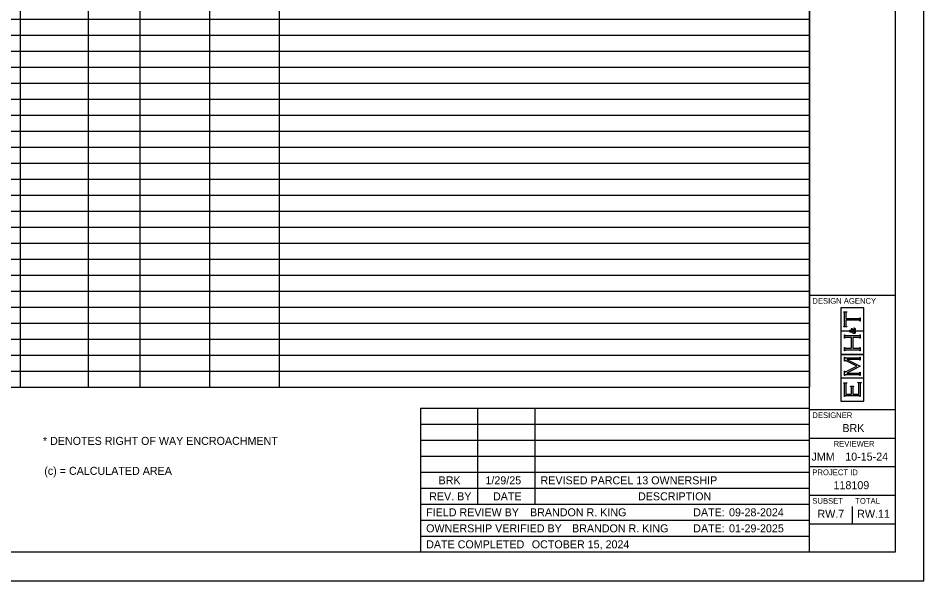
# Model space of a CAD drawing. Extents: x 0 to 34, y 0 to 22.
# Drawn here: x 18.16 to 34, y 0 to 9.85 of the extents above; entities that cross this region are included whole.
import ezdxf

# ---------------------------------------------------------------- set-up
doc = ezdxf.new("R2010")
doc.units = 0
for name, color, linetype in [('SH_Border', 7, 'Continuous'), ('SH_Cut_Line', 7, 'Continuous'), ('SH_Data', 7, 'Continuous'), ('SH_Text', 7, 'Continuous')]:
    doc.layers.add(name, color=color, linetype=linetype)

msp = doc.modelspace()

# ---------------------------------------------------------------- linework, layer by layer
at = {"layer": 'SH_Border'}
for p, q in [((32, 0.5), (32, 21.5)), ((32, 5), (33.5, 5)), ((32, 3), (33.5, 3)), ((32, 2.5), (33.5, 2.5)), ((32, 2), (33.5, 2)), ((32, 1.5), (33.5, 1.5)), ((32, 1), (33.5, 1))]:
    msp.add_line(p, q, dxfattribs=at)
msp.add_lwpolyline([(1.5, 21.5), (33.5, 21.5), (33.5, 0.5), (1.5, 0.5)], close=True, dxfattribs=at)
at = {"layer": 'SH_Cut_Line'}
msp.add_lwpolyline([(0, 0), (34, 0), (34, 22), (0, 22)], close=True, dxfattribs=at)
at = {"layer": 'SH_Data'}
for p, q in [((32.952, 4.779), (32.547, 4.779)), ((32.547, 4.779), (32.547, 4.375)), ((32.952, 4.375), (32.952, 4.779)), ((32.598, 4.704), (32.598, 4.711)), ((32.598, 4.711), (32.65, 4.711)), ((32.603, 4.703), (32.598, 4.704)), ((32.606, 4.701), (32.603, 4.703)), ((32.608, 4.699), (32.606, 4.701)), ((32.61, 4.696), (32.608, 4.699)), ((32.611, 4.692), (32.61, 4.696)), ((32.611, 4.687), (32.611, 4.692)), ((32.611, 4.468), (32.611, 4.687)), ((32.638, 4.696), (32.637, 4.692)), ((32.637, 4.692), (32.637, 4.687)), ((32.637, 4.687), (32.637, 4.593)), ((32.637, 4.593), (32.864, 4.593)), ((32.64, 4.699), (32.638, 4.696)), ((32.642, 4.701), (32.64, 4.699)), ((32.645, 4.703), (32.642, 4.701)), ((32.65, 4.704), (32.645, 4.703)), ((32.65, 4.711), (32.65, 4.704)), ((32.864, 4.593), (32.869, 4.593)), ((32.869, 4.593), (32.873, 4.594)), ((32.873, 4.594), (32.876, 4.596)), ((32.876, 4.596), (32.878, 4.597)), ((32.878, 4.597), (32.88, 4.601)), ((32.88, 4.601), (32.881, 4.606)), ((32.881, 4.606), (32.888, 4.606)), ((32.888, 4.606), (32.888, 4.548)), ((32.598, 4.45), (32.603, 4.451)), ((32.598, 4.444), (32.598, 4.45)), ((32.65, 4.444), (32.598, 4.444)), ((32.603, 4.451), (32.606, 4.453)), ((32.606, 4.453), (32.608, 4.455)), ((32.608, 4.455), (32.61, 4.458)), ((32.61, 4.458), (32.611, 4.462)), ((32.611, 4.462), (32.611, 4.468)), ((32.864, 4.561), (32.637, 4.561)), ((32.637, 4.561), (32.637, 4.468)), ((32.637, 4.468), (32.637, 4.462)), ((32.637, 4.462), (32.638, 4.458)), ((32.638, 4.458), (32.64, 4.455)), ((32.64, 4.455), (32.642, 4.453)), ((32.642, 4.453), (32.645, 4.451)), ((32.645, 4.451), (32.65, 4.45)), ((32.65, 4.45), (32.65, 4.444)), ((32.87, 4.561), (32.864, 4.561)), ((32.874, 4.56), (32.87, 4.561)), ((32.876, 4.559), (32.874, 4.56)), ((32.878, 4.557), (32.876, 4.559)), ((32.88, 4.553), (32.878, 4.557)), ((32.881, 4.548), (32.88, 4.553)), ((32.888, 4.548), (32.881, 4.548)), ((32.547, 4.375), (32.696, 4.375)), ((32.696, 4.369), (32.547, 4.369)), ((32.547, 4.369), (32.547, 3.965)), ((32.611, 4.249), (32.611, 4.307)), ((32.611, 4.307), (32.617, 4.307)), ((32.617, 4.307), (32.619, 4.302)), ((32.619, 4.302), (32.62, 4.298)), ((32.62, 4.298), (32.623, 4.297)), ((32.623, 4.297), (32.625, 4.295)), ((32.625, 4.295), (32.629, 4.294)), ((32.629, 4.294), (32.635, 4.294)), ((32.635, 4.294), (32.864, 4.294)), ((32.696, 4.375), (32.696, 4.369)), ((32.703, 4.379), (32.705, 4.383)), ((32.703, 4.373), (32.703, 4.379)), ((32.703, 4.368), (32.703, 4.373)), ((32.705, 4.363), (32.703, 4.368)), ((32.705, 4.383), (32.708, 4.387)), ((32.708, 4.358), (32.705, 4.363)), ((32.708, 4.387), (32.711, 4.39)), ((32.709, 4.379), (32.708, 4.376)), ((32.708, 4.376), (32.708, 4.373)), ((32.708, 4.373), (32.708, 4.369)), ((32.708, 4.369), (32.71, 4.366)), ((32.712, 4.353), (32.708, 4.358)), ((32.712, 4.381), (32.709, 4.379)), ((32.71, 4.366), (32.712, 4.364)), ((32.711, 4.39), (32.715, 4.392)), ((32.714, 4.383), (32.712, 4.381)), ((32.712, 4.364), (32.715, 4.362)), ((32.718, 4.35), (32.712, 4.353)), ((32.716, 4.384), (32.714, 4.383)), ((32.715, 4.392), (32.72, 4.392)), ((32.715, 4.362), (32.718, 4.361)), ((32.72, 4.384), (32.716, 4.384)), ((32.718, 4.361), (32.721, 4.361)), ((32.726, 4.35), (32.718, 4.35)), ((32.72, 4.392), (32.725, 4.392)), ((32.724, 4.384), (32.72, 4.384)), ((32.721, 4.361), (32.723, 4.361)), ((32.723, 4.361), (32.725, 4.362)), ((32.728, 4.382), (32.724, 4.384)), ((32.725, 4.392), (32.729, 4.39)), ((32.725, 4.362), (32.728, 4.362)), ((32.729, 4.35), (32.726, 4.35)), ((32.731, 4.38), (32.728, 4.382)), ((32.728, 4.362), (32.731, 4.363)), ((32.729, 4.39), (32.732, 4.387)), ((32.731, 4.35), (32.729, 4.35)), ((32.734, 4.377), (32.731, 4.38)), ((32.731, 4.363), (32.735, 4.365)), ((32.734, 4.351), (32.731, 4.35)), ((32.732, 4.387), (32.736, 4.383)), ((32.737, 4.372), (32.734, 4.377)), ((32.737, 4.352), (32.734, 4.351)), ((32.735, 4.365), (32.74, 4.367)), ((32.736, 4.383), (32.74, 4.378)), ((32.74, 4.367), (32.737, 4.372)), ((32.741, 4.353), (32.737, 4.352)), ((32.738, 4.393), (32.738, 4.422)), ((32.738, 4.422), (32.741, 4.422)), ((32.741, 4.393), (32.738, 4.393)), ((32.74, 4.378), (32.744, 4.369)), ((32.741, 4.422), (32.741, 4.418)), ((32.741, 4.418), (32.742, 4.415)), ((32.742, 4.396), (32.741, 4.395)), ((32.741, 4.395), (32.741, 4.393)), ((32.746, 4.355), (32.741, 4.353)), ((32.742, 4.415), (32.743, 4.413)), ((32.743, 4.397), (32.742, 4.396)), ((32.743, 4.413), (32.745, 4.411)), ((32.745, 4.399), (32.743, 4.397)), ((32.744, 4.369), (32.754, 4.375)), ((32.745, 4.411), (32.749, 4.408)), ((32.746, 4.399), (32.745, 4.399)), ((32.748, 4.399), (32.746, 4.399)), ((32.752, 4.344), (32.746, 4.355)), ((32.755, 4.399), (32.748, 4.399)), ((32.749, 4.408), (32.756, 4.404)), ((32.756, 4.36), (32.751, 4.357)), ((32.751, 4.357), (32.754, 4.352)), ((32.757, 4.337), (32.752, 4.344)), ((32.754, 4.375), (32.764, 4.381)), ((32.754, 4.352), (32.757, 4.348)), ((32.763, 4.395), (32.755, 4.399)), ((32.756, 4.404), (32.763, 4.4)), ((32.761, 4.363), (32.756, 4.36)), ((32.757, 4.348), (32.761, 4.345)), ((32.763, 4.333), (32.757, 4.337)), ((32.764, 4.365), (32.761, 4.363)), ((32.761, 4.345), (32.765, 4.343)), ((32.763, 4.4), (32.77, 4.396)), ((32.772, 4.387), (32.763, 4.395)), ((32.768, 4.329), (32.763, 4.333)), ((32.764, 4.381), (32.772, 4.387)), ((32.768, 4.367), (32.764, 4.365)), ((32.765, 4.343), (32.769, 4.341)), ((32.774, 4.372), (32.768, 4.367)), ((32.774, 4.327), (32.768, 4.329)), ((32.769, 4.341), (32.773, 4.341)), ((32.77, 4.396), (32.776, 4.391)), ((32.773, 4.341), (32.778, 4.341)), ((32.782, 4.378), (32.774, 4.372)), ((32.779, 4.327), (32.774, 4.327)), ((32.776, 4.391), (32.781, 4.395)), ((32.778, 4.341), (32.782, 4.343)), ((32.779, 4.423), (32.781, 4.426)), ((32.782, 4.422), (32.779, 4.423)), ((32.785, 4.327), (32.779, 4.327)), ((32.781, 4.426), (32.787, 4.424)), ((32.781, 4.395), (32.784, 4.398)), ((32.785, 4.421), (32.782, 4.422)), ((32.786, 4.373), (32.782, 4.378)), ((32.782, 4.343), (32.786, 4.346)), ((32.784, 4.398), (32.786, 4.401)), ((32.786, 4.419), (32.785, 4.421)), ((32.79, 4.329), (32.785, 4.327)), ((32.788, 4.417), (32.786, 4.419)), ((32.786, 4.401), (32.788, 4.404)), ((32.791, 4.386), (32.786, 4.381)), ((32.786, 4.381), (32.791, 4.376)), ((32.788, 4.369), (32.786, 4.373)), ((32.786, 4.346), (32.789, 4.349)), ((32.787, 4.424), (32.792, 4.421)), ((32.789, 4.414), (32.788, 4.417)), ((32.788, 4.404), (32.789, 4.408)), ((32.79, 4.367), (32.788, 4.369)), ((32.789, 4.411), (32.789, 4.414)), ((32.789, 4.408), (32.789, 4.411)), ((32.789, 4.349), (32.791, 4.353)), ((32.791, 4.364), (32.79, 4.367)), ((32.793, 4.334), (32.79, 4.329)), ((32.794, 4.39), (32.791, 4.386)), ((32.791, 4.376), (32.795, 4.37)), ((32.791, 4.361), (32.791, 4.364)), ((32.791, 4.359), (32.791, 4.361)), ((32.791, 4.353), (32.791, 4.359)), ((32.792, 4.421), (32.795, 4.418)), ((32.797, 4.338), (32.793, 4.334)), ((32.796, 4.394), (32.794, 4.39)), ((32.795, 4.418), (32.798, 4.414)), ((32.795, 4.37), (32.797, 4.366)), ((32.798, 4.397), (32.796, 4.394)), ((32.797, 4.366), (32.798, 4.361)), ((32.799, 4.344), (32.797, 4.338)), ((32.798, 4.414), (32.799, 4.41)), ((32.799, 4.401), (32.798, 4.397)), ((32.798, 4.361), (32.799, 4.357)), ((32.799, 4.41), (32.799, 4.405)), ((32.799, 4.405), (32.799, 4.401)), ((32.803, 4.369), (32.799, 4.375)), ((32.799, 4.375), (32.952, 4.375)), ((32.799, 4.357), (32.799, 4.352)), ((32.799, 4.352), (32.799, 4.344)), ((32.952, 4.369), (32.803, 4.369)), ((32.864, 4.294), (32.869, 4.294)), ((32.869, 4.294), (32.873, 4.295)), ((32.873, 4.295), (32.876, 4.297)), ((32.876, 4.297), (32.878, 4.298)), ((32.878, 4.298), (32.88, 4.302)), ((32.88, 4.302), (32.881, 4.307)), ((32.881, 4.307), (32.888, 4.307)), ((32.888, 4.307), (32.888, 4.249)), ((32.952, 3.965), (32.952, 4.369)), ((32.617, 4.249), (32.611, 4.249)), ((32.618, 4.254), (32.617, 4.249)), ((32.62, 4.258), (32.618, 4.254)), ((32.623, 4.26), (32.62, 4.258)), ((32.625, 4.261), (32.623, 4.26)), ((32.629, 4.262), (32.625, 4.261)), ((32.635, 4.262), (32.629, 4.262)), ((32.732, 4.262), (32.635, 4.262)), ((32.732, 4.072), (32.732, 4.262)), ((32.864, 4.262), (32.759, 4.262)), ((32.759, 4.262), (32.759, 4.072)), ((32.87, 4.262), (32.864, 4.262)), ((32.874, 4.261), (32.87, 4.262)), ((32.876, 4.26), (32.874, 4.261)), ((32.878, 4.258), (32.876, 4.26)), ((32.88, 4.254), (32.878, 4.258)), ((32.881, 4.249), (32.88, 4.254)), ((32.888, 4.249), (32.881, 4.249)), ((32.547, 3.965), (32.952, 3.965)), ((32.611, 4.027), (32.611, 4.085)), ((32.611, 4.085), (32.617, 4.085)), ((32.617, 4.027), (32.611, 4.027)), ((32.617, 4.085), (32.619, 4.08)), ((32.618, 4.032), (32.617, 4.027)), ((32.62, 4.036), (32.618, 4.032)), ((32.619, 4.08), (32.62, 4.076)), ((32.62, 4.076), (32.623, 4.074)), ((32.623, 4.037), (32.62, 4.036)), ((32.623, 4.074), (32.625, 4.073)), ((32.625, 4.039), (32.623, 4.037)), ((32.625, 4.073), (32.629, 4.072)), ((32.629, 4.04), (32.625, 4.039)), ((32.629, 4.072), (32.635, 4.072)), ((32.635, 4.04), (32.629, 4.04)), ((32.635, 4.072), (32.732, 4.072)), ((32.864, 4.04), (32.635, 4.04)), ((32.75, 4), (32.75, 4)), ((32.759, 4.072), (32.864, 4.072)), ((32.864, 4.072), (32.87, 4.072)), ((32.87, 4.04), (32.864, 4.04)), ((32.87, 4.072), (32.874, 4.073)), ((32.874, 4.039), (32.87, 4.04)), ((32.874, 4.073), (32.876, 4.074)), ((32.876, 4.038), (32.874, 4.039)), ((32.876, 4.074), (32.878, 4.076)), ((32.878, 4.036), (32.876, 4.038)), ((32.878, 4.076), (32.88, 4.08)), ((32.88, 4.032), (32.878, 4.036)), ((32.88, 4.08), (32.881, 4.085)), ((32.881, 4.027), (32.88, 4.032)), ((32.881, 4.085), (32.888, 4.085)), ((32.888, 4.027), (32.881, 4.027)), ((32.888, 4.085), (32.888, 4.027)), ((32.952, 3.959), (32.547, 3.959)), ((32.547, 3.959), (32.547, 3.555)), ((32.611, 3.845), (32.611, 3.918)), ((32.611, 3.918), (32.617, 3.918)), ((32.617, 3.845), (32.611, 3.845)), ((32.617, 3.918), (32.619, 3.912)), ((32.62, 3.852), (32.617, 3.845)), ((32.619, 3.912), (32.62, 3.909)), ((32.62, 3.909), (32.623, 3.907)), ((32.622, 3.855), (32.62, 3.852)), ((32.626, 3.855), (32.622, 3.855)), ((32.623, 3.907), (32.625, 3.905)), ((32.625, 3.905), (32.629, 3.905)), ((32.629, 3.855), (32.626, 3.855)), ((32.629, 3.905), (32.635, 3.905)), ((32.633, 3.853), (32.629, 3.855)), ((32.64, 3.85), (32.633, 3.853)), ((32.635, 3.905), (32.864, 3.905)), ((32.825, 3.757), (32.64, 3.85)), ((32.864, 3.873), (32.654, 3.873)), ((32.654, 3.873), (32.888, 3.755)), ((32.864, 3.905), (32.869, 3.905)), ((32.87, 3.873), (32.864, 3.873)), ((32.869, 3.905), (32.873, 3.905)), ((32.874, 3.872), (32.87, 3.873)), ((32.873, 3.905), (32.876, 3.907)), ((32.876, 3.87), (32.874, 3.872)), ((32.876, 3.907), (32.878, 3.909)), ((32.878, 3.869), (32.876, 3.87)), ((32.878, 3.909), (32.88, 3.912)), ((32.88, 3.865), (32.878, 3.869)), ((32.88, 3.912), (32.881, 3.918)), ((32.881, 3.86), (32.88, 3.865)), ((32.881, 3.918), (32.888, 3.918)), ((32.888, 3.86), (32.881, 3.86)), ((32.888, 3.918), (32.888, 3.86)), ((32.952, 3.555), (32.952, 3.959)), ((32.611, 3.596), (32.611, 3.668)), ((32.611, 3.668), (32.617, 3.668)), ((32.617, 3.668), (32.62, 3.662)), ((32.62, 3.662), (32.622, 3.658)), ((32.622, 3.658), (32.626, 3.658)), ((32.626, 3.658), (32.627, 3.658)), ((32.627, 3.658), (32.633, 3.661)), ((32.633, 3.661), (32.641, 3.665)), ((32.641, 3.665), (32.825, 3.757)), ((32.888, 3.755), (32.654, 3.638)), ((32.876, 3.641), (32.878, 3.643)), ((32.878, 3.643), (32.88, 3.646)), ((32.88, 3.646), (32.881, 3.651)), ((32.881, 3.651), (32.888, 3.651)), ((32.888, 3.651), (32.888, 3.596)), ((32.547, 3.555), (32.952, 3.555)), ((32.952, 3.549), (32.547, 3.549)), ((32.547, 3.549), (32.547, 3.145)), ((32.617, 3.596), (32.611, 3.596)), ((32.618, 3.602), (32.617, 3.596)), ((32.62, 3.605), (32.618, 3.602)), ((32.623, 3.607), (32.62, 3.605)), ((32.625, 3.609), (32.623, 3.607)), ((32.629, 3.609), (32.625, 3.609)), ((32.635, 3.609), (32.629, 3.609)), ((32.864, 3.609), (32.635, 3.609)), ((32.654, 3.638), (32.864, 3.638)), ((32.864, 3.638), (32.869, 3.638)), ((32.87, 3.609), (32.864, 3.609)), ((32.869, 3.638), (32.873, 3.639)), ((32.874, 3.609), (32.87, 3.609)), ((32.873, 3.639), (32.876, 3.641)), ((32.876, 3.607), (32.874, 3.609)), ((32.878, 3.605), (32.876, 3.607)), ((32.88, 3.602), (32.878, 3.605)), ((32.881, 3.596), (32.88, 3.602)), ((32.888, 3.596), (32.881, 3.596)), ((32.952, 3.145), (32.952, 3.549)), ((32.598, 3.462), (32.598, 3.469)), ((32.598, 3.469), (32.65, 3.469)), ((32.603, 3.461), (32.598, 3.462)), ((32.606, 3.459), (32.603, 3.461)), ((32.608, 3.457), (32.606, 3.459)), ((32.61, 3.455), (32.608, 3.457)), ((32.611, 3.451), (32.61, 3.455)), ((32.611, 3.445), (32.611, 3.451)), ((32.611, 3.225), (32.611, 3.445)), ((32.64, 3.457), (32.638, 3.455)), ((32.638, 3.455), (32.638, 3.451)), ((32.638, 3.451), (32.638, 3.445)), ((32.638, 3.445), (32.638, 3.27)), ((32.642, 3.459), (32.64, 3.457)), ((32.645, 3.461), (32.642, 3.459)), ((32.65, 3.462), (32.645, 3.461)), ((32.65, 3.469), (32.65, 3.462)), ((32.719, 3.402), (32.719, 3.408)), ((32.719, 3.408), (32.772, 3.408)), ((32.724, 3.401), (32.719, 3.402)), ((32.728, 3.399), (32.724, 3.401)), ((32.729, 3.396), (32.728, 3.399)), ((32.731, 3.394), (32.729, 3.396)), ((32.732, 3.39), (32.731, 3.394)), ((32.732, 3.384), (32.732, 3.39)), ((32.732, 3.27), (32.732, 3.384)), ((32.76, 3.394), (32.759, 3.39)), ((32.759, 3.39), (32.759, 3.384)), ((32.759, 3.384), (32.759, 3.27)), ((32.761, 3.396), (32.76, 3.394)), ((32.763, 3.399), (32.761, 3.396)), ((32.767, 3.401), (32.763, 3.399)), ((32.772, 3.402), (32.767, 3.401)), ((32.772, 3.408), (32.772, 3.402)), ((32.848, 3.465), (32.848, 3.472)), ((32.848, 3.472), (32.901, 3.472)), ((32.853, 3.464), (32.848, 3.465)), ((32.857, 3.462), (32.853, 3.464)), ((32.859, 3.46), (32.857, 3.462)), ((32.86, 3.458), (32.859, 3.46)), ((32.861, 3.453), (32.86, 3.458)), ((32.861, 3.448), (32.861, 3.453)), ((32.861, 3.27), (32.861, 3.448)), ((32.889, 3.457), (32.888, 3.453)), ((32.888, 3.453), (32.888, 3.448)), ((32.888, 3.448), (32.888, 3.225)), ((32.891, 3.46), (32.889, 3.457)), ((32.892, 3.462), (32.891, 3.46)), ((32.896, 3.464), (32.892, 3.462)), ((32.901, 3.465), (32.896, 3.464)), ((32.901, 3.472), (32.901, 3.465)), ((32.617, 3.225), (32.611, 3.225)), ((32.619, 3.23), (32.617, 3.225)), ((32.62, 3.234), (32.619, 3.23)), ((32.623, 3.235), (32.62, 3.234)), ((32.625, 3.237), (32.623, 3.235)), ((32.629, 3.238), (32.625, 3.237)), ((32.635, 3.238), (32.629, 3.238)), ((32.864, 3.238), (32.635, 3.238)), ((32.638, 3.27), (32.732, 3.27)), ((32.759, 3.27), (32.861, 3.27)), ((32.87, 3.238), (32.864, 3.238)), ((32.874, 3.237), (32.87, 3.238)), ((32.876, 3.235), (32.874, 3.237)), ((32.878, 3.234), (32.876, 3.235)), ((32.88, 3.23), (32.878, 3.234)), ((32.881, 3.225), (32.88, 3.23)), ((32.888, 3.225), (32.881, 3.225)), ((32.547, 3.145), (32.952, 3.145)), ((32.75, 1), (32.75, 1.3))]:
    msp.add_line(p, q, dxfattribs=at)
at = {"layer": 'SH_Text'}
for p, q in [((18.199, 19.957), (18.199, 3.39)), ((19.385, 19.957), (19.385, 3.39)), ((20.291, 19.957), (20.291, 3.39)), ((22.728, 19.957), (22.728, 3.39)), ((32, 19.957), (32, 3.39)), ((21.509, 19.661), (21.509, 3.39)), ((1.5, 9.829), (32, 9.829)), ((1.5, 9.549), (32, 9.549)), ((1.5, 9.269), (32, 9.269)), ((1.5, 8.989), (32, 8.989)), ((1.5, 8.709), (32, 8.709)), ((1.5, 8.429), (32, 8.429)), ((1.5, 8.149), (32, 8.149)), ((1.5, 7.869), (32, 7.869)), ((1.5, 7.589), (32, 7.589)), ((1.5, 7.309), (32, 7.309)), ((1.5, 7.029), (32, 7.029)), ((1.5, 6.749), (32, 6.749)), ((1.5, 6.469), (32, 6.469)), ((1.5, 6.189), (32, 6.189)), ((1.5, 5.909), (32, 5.909)), ((1.5, 5.629), (32, 5.629)), ((1.5, 5.349), (32, 5.349)), ((1.5, 5.069), (32, 5.069)), ((1.5, 4.789), (32, 4.789)), ((1.5, 4.509), (32, 4.509)), ((1.5, 4.23), (32, 4.23)), ((1.5, 3.95), (32, 3.95)), ((1.5, 3.67), (32, 3.67)), ((1.5, 3.39), (32, 3.39)), ((25.197, 3.02), (25.197, 0.5)), ((25.197, 3.02), (32, 3.02)), ((26.197, 3.02), (26.197, 1.34)), ((27.197, 3.02), (27.197, 1.34)), ((25.197, 2.74), (32, 2.74)), ((25.197, 2.46), (32, 2.46)), ((25.197, 2.18), (32, 2.18)), ((25.197, 1.9), (32, 1.9)), ((25.197, 1.62), (32, 1.62)), ((25.197, 1.34), (32, 1.34)), ((25.197, 1.06), (32, 1.06)), ((25.197, 0.78), (32, 0.78)), ((32, 0.5), (32, 0.5))]:
    msp.add_line(p, q, dxfattribs=at)

# ---------------------------------------------------------------- texts
at = {"layer": 'SH_Data'}
for s, height, p in [('DESIGN AGENCY', 0.1, (32.05, 4.85)), ('DESIGNER', 0.1, (32.05, 2.85)), ('BRK', 0.14, (32.575, 2.605)), ('REVIEWER', 0.1, (32.422, 2.35)), ('JMM', 0.14, (32.035, 2.105)), ('10-15-24', 0.14, (32.625, 2.105)), ('PROJECT ID', 0.1, (32.05, 1.85)), ('SUBSET', 0.1, (32.05, 1.35)), ('TOTAL', 0.1, (32.8, 1.35)), ('RW.7', 0.14, (32.139, 1.105)), ('RW.11', 0.14, (32.834, 1.105))]:
    msp.add_text(s, height=height, dxfattribs=at).set_placement(p)
at = {"layer": 'SH_Text'}
for s, p in [('* DENOTES RIGHT OF WAY ENCROACHMENT', (18.596, 2.38)), ('(c) = CALCULATED AREA', (18.62, 1.856)), ('BRK', (25.515, 1.69)), ('1/29/25', (26.334, 1.69)), ('REVISED PARCEL 13 OWNERSHIP', (27.297, 1.69)), ('118109', (32.42, 1.605)), ('REV. BY', (25.35, 1.41)), ('DATE', (26.466, 1.41)), ('DESCRIPTION', (29.002, 1.41)), ('FIELD REVIEW BY', (25.297, 1.13)), ('BRANDON R. KING', (27.113, 1.13)), ('DATE:', (29.967, 1.13)), ('09-28-2024', (30.593, 1.13)), ('OWNERSHIP VERIFIED BY', (25.297, 0.85)), ('BRANDON R. KING', (27.848, 0.85)), ('DATE:', (29.967, 0.85)), ('01-29-2025', (30.593, 0.85)), ('DATE COMPLETED', (25.297, 0.57)), ('OCTOBER 15, 2024', (27.144, 0.57))]:
    msp.add_text(s, height=0.14, dxfattribs=at).set_placement(p)

doc.saveas('drawing.dxf')
